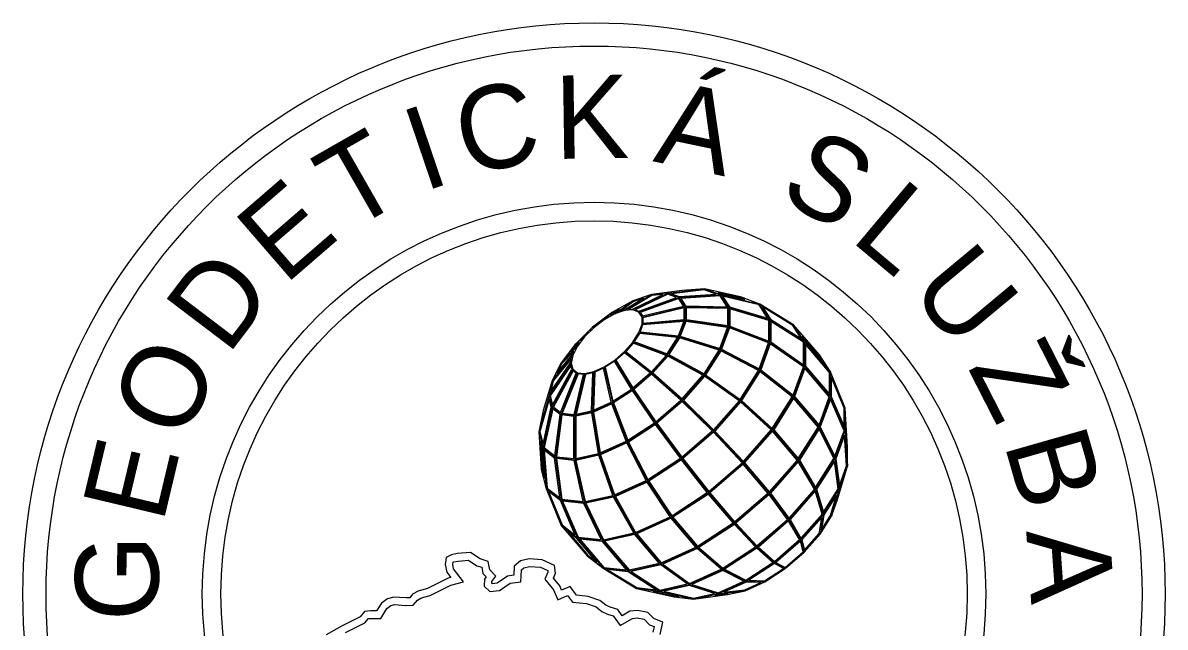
# Model space of a CAD drawing. Extents: x 70 to 280, y -123 to 174.
# Drawn here: x 204.6 to 220.99, y -1.41 to 7.26 of the extents above; entities that cross this region are included whole.
import ezdxf

# ---------------------------------------------------------------- set-up
doc = ezdxf.new("R2010")
doc.units = 0
doc.layers.add('Vrstva 63', color=7, linetype='Continuous')

msp = doc.modelspace()

# ---------------------------------------------------------------- linework, layer by layer
at = {"layer": 'Vrstva 63'}
for p, q in [((213.234, 3.131), (213.622, 3.361)), ((213.092, 3.082), (213.35, 3.268)), ((212.94, 2.998), (213.059, 3.106)), ((212.792, 2.885), (212.774, 2.891)), ((212.66, 2.755), (212.521, 2.641)), ((212.49, 2.488), (212.195, 2.128)), ((212.556, 2.619), (212.322, 2.379)), ((216.42, 1.169), (216.385, 1.729))]:
    msp.add_line(p, q, dxfattribs=at)
for points in [[(212.521, 2.641), (212.322, 2.379), (212.195, 2.128), (212.064, 1.694), (212.003, 1.389), (212.036, 0.855), (212.109, 0.577), (212.325, 0.047), (212.695, -0.388), (212.928, -0.568), (213.403, -0.858), (213.945, -0.98), (214.223, -1.011), (214.709, -0.947), (214.962, -0.891), (215.247, -0.762), (215.538, -0.571), (215.81, -0.336), (216.039, -0.077), (216.204, 0.182), (216.29, 0.42), (216.433, 0.899), (216.433, 1.17), (216.398, 1.73), (216.187, 2.249), (216.029, 2.493), (215.659, 2.928), (215.173, 3.224), (214.895, 3.326), (214.379, 3.442), (214.06, 3.418), (213.622, 3.361), (213.35, 3.268), (213.059, 3.106), (212.774, 2.891)], [(213.173, 3.124), (213.228, 3.143), (213.505, 3.307), (213.356, 3.256)], [(213.289, 3.148), (213.349, 3.153), (213.782, 3.36), (213.626, 3.348)], [(213.852, 3.364), (213.387, 3.141), (213.439, 3.122), (213.977, 3.318)], [(213.459, 3.101), (213.49, 3.053), (214.08, 3.193), (214.01, 3.302)], [(213.907, 3.372), (214.018, 3.331), (214.547, 3.367), (214.378, 3.429)], [(214.039, 3.306), (214.109, 3.198), (214.705, 3.185), (214.603, 3.344)], [(214.573, 3.385), (214.613, 3.37), (214.961, 3.288), (214.892, 3.313)], [(214.639, 3.337), (214.739, 3.183), (215.287, 3.023), (215.164, 3.212)], [(212.94, 2.322), (213.092, 2.421), (213.234, 2.544), (213.353, 2.678), (213.439, 2.814), (213.484, 2.937), (213.484, 3.038), (213.439, 3.108), (213.353, 3.139), (213.234, 3.131), (213.092, 3.082), (212.94, 2.998), (212.792, 2.885), (212.66, 2.755), (212.556, 2.619), (212.49, 2.488), (212.467, 2.374), (212.49, 2.288), (212.556, 2.237), (212.66, 2.225), (212.792, 2.254)], [(213.067, 3.095), (213.032, 3.064), (213.085, 3.093), (213.16, 3.147)], [(214.089, 3.168), (213.497, 3.028), (213.497, 2.952), (214.089, 3.003)], [(214.115, 3.171), (214.115, 3.002), (214.717, 2.916), (214.717, 3.158)], [(214.743, 3.154), (214.743, 2.909), (215.304, 2.693), (215.304, 2.99)], [(215.215, 3.182), (215.327, 3.009), (215.772, 2.727), (215.649, 2.918)], [(214.082, 2.976), (213.493, 2.925), (213.457, 2.825), (214.007, 2.768)], [(214.712, 2.89), (214.111, 2.976), (214.033, 2.762), (214.601, 2.585)], [(215.331, 2.976), (215.331, 2.681), (215.803, 2.354), (215.803, 2.676)], [(212.76, 2.859), (212.735, 2.835)], [(212.79, 2.887), (212.802, 2.896)], [(213.993, 2.742), (213.446, 2.8), (213.373, 2.685), (213.845, 2.51)], [(215.301, 2.666), (214.738, 2.883), (214.626, 2.575), (215.165, 2.293)], [(212.46, 2.54), (212.546, 2.627), (212.581, 2.674), (212.53, 2.632)], [(213.828, 2.488), (213.357, 2.663), (213.253, 2.545), (213.621, 2.253)], [(214.589, 2.561), (214.021, 2.738), (213.87, 2.499), (214.375, 2.223)], [(215.801, 2.324), (215.324, 2.653), (215.188, 2.279), (215.652, 1.916)], [(215.78, 2.765), (215.827, 2.692), (216.065, 2.412), (216.018, 2.485)], [(215.83, 2.648), (215.83, 2.334), (216.173, 1.93), (216.173, 2.244)], [(212.261, 2.23), (212.479, 2.495), (212.505, 2.548), (212.333, 2.371)], [(213.602, 2.235), (213.234, 2.526), (213.109, 2.418), (213.353, 2.02)], [(214.358, 2.202), (213.854, 2.477), (213.641, 2.236), (214.059, 1.863)], [(215.154, 2.269), (214.614, 2.551), (214.397, 2.209), (214.892, 1.856)], [(212.199, 1.78), (212.476, 2.29), (212.462, 2.343), (212.166, 1.907)], [(212.177, 1.971), (212.455, 2.379), (212.466, 2.438), (212.207, 2.122)], [(212.931, 2.303), (212.805, 2.246), (212.788, 1.701), (213.043, 1.817)], [(213.088, 2.402), (212.955, 2.316), (213.067, 1.831), (213.332, 2.004)], [(215.821, 2.303), (215.674, 1.897), (216.024, 1.485), (216.172, 1.891)], [(212.316, 1.668), (212.54, 2.232), (212.494, 2.268), (212.212, 1.748)], [(212.643, 2.214), (212.565, 2.222), (212.34, 1.658), (212.51, 1.639)], [(212.761, 1.691), (212.778, 2.238), (212.671, 2.214), (212.538, 1.642)], [(214.04, 1.844), (213.622, 2.217), (213.368, 1.997), (213.682, 1.535)], [(214.876, 1.835), (214.381, 2.188), (214.078, 1.845), (214.51, 1.421)], [(215.176, 2.255), (214.913, 1.84), (215.354, 1.439), (215.641, 1.891)], [(216.2, 2.181), (216.2, 1.897), (216.385, 1.468), (216.385, 1.728)], [(213.661, 1.519), (213.347, 1.982), (213.075, 1.804), (213.278, 1.269)], [(212.063, 1.214), (212.181, 1.744), (212.151, 1.859), (212.017, 1.389)], [(214.491, 1.403), (214.059, 1.826), (213.697, 1.513), (214.055, 1.026)], [(214.896, 1.819), (214.529, 1.402), (214.938, 0.965), (215.339, 1.418)], [(215.66, 1.872), (215.374, 1.42), (215.726, 1.006), (216.012, 1.458)], [(216.384, 1.404), (216.188, 1.858), (216.043, 1.46), (216.251, 1.039)], [(212.231, 1.046), (212.308, 1.64), (212.203, 1.721), (212.079, 1.163)], [(212.763, 1.664), (212.534, 1.614), (212.533, 1.007), (212.858, 1.079)], [(213.255, 1.256), (213.051, 1.791), (212.788, 1.672), (212.884, 1.088)], [(212.506, 1.005), (212.507, 1.612), (212.333, 1.632), (212.257, 1.033)], [(214.034, 1.01), (213.676, 1.497), (213.289, 1.244), (213.568, 0.705)], [(214.92, 0.946), (214.51, 1.384), (214.071, 1.005), (214.442, 0.534)], [(215.357, 1.399), (214.956, 0.945), (215.309, 0.53), (215.71, 0.984)], [(216.238, 1.006), (216.027, 1.432), (215.743, 0.984), (215.976, 0.593)], [(216.42, 0.901), (216.389, 1.341), (216.267, 1.003), (216.319, 0.622)], [(212.085, 0.722), (212.051, 1.156), (212.025, 1.256), (212.049, 0.857)], [(213.544, 0.692), (213.266, 1.231), (212.89, 1.061), (213.091, 0.487)], [(212.305, 0.442), (212.229, 1.014), (212.08, 1.129), (212.122, 0.583)], [(212.64, 0.39), (212.509, 0.978), (212.257, 1.006), (212.334, 0.424)], [(213.065, 0.478), (212.865, 1.053), (212.535, 0.98), (212.667, 0.39)], [(214.421, 0.518), (214.05, 0.989), (213.581, 0.682), (213.911, 0.184)], [(214.937, 0.926), (214.459, 0.513), (214.812, 0.098), (215.29, 0.512)], [(215.96, 0.569), (215.725, 0.962), (215.326, 0.509), (215.592, 0.153)], [(216.299, 0.57), (216.245, 0.967), (215.99, 0.566), (216.087, 0.236)], [(213.887, 0.171), (213.558, 0.669), (213.102, 0.463), (213.391, -0.053)], [(212.525, -0.091), (212.312, 0.403), (212.14, 0.536), (212.336, 0.055)], [(214.791, 0.082), (214.438, 0.497), (213.927, 0.163), (214.279, -0.252)], [(216.068, 0.208), (215.97, 0.541), (215.608, 0.131), (215.765, -0.135)], [(212.899, -0.157), (212.648, 0.362), (212.344, 0.396), (212.567, -0.12)], [(213.365, -0.061), (213.076, 0.454), (212.676, 0.365), (212.929, -0.158)], [(215.573, 0.134), (215.307, 0.491), (214.83, 0.079), (215.134, -0.245)], [(216.191, 0.188), (216.275, 0.483), (216.095, 0.2), (216.062, -0.016)], [(214.255, -0.264), (213.903, 0.149), (213.407, -0.075), (213.759, -0.489)], [(215.113, -0.261), (214.809, 0.062), (214.299, -0.271), (214.644, -0.567)], [(215.746, -0.155), (215.588, 0.112), (215.154, -0.263), (215.383, -0.469)], [(216.063, 0.162), (215.778, -0.161), (215.817, -0.309), (216.026, -0.071)], [(212.835, -0.479), (212.548, -0.142), (212.418, -0.042), (212.705, -0.378)], [(213.26, -0.591), (212.915, -0.186), (212.589, -0.15), (212.934, -0.555)], [(213.731, -0.497), (213.38, -0.085), (212.946, -0.181), (213.297, -0.593)], [(214.619, -0.58), (214.275, -0.285), (213.781, -0.508), (214.165, -0.786)], [(215.361, -0.485), (215.132, -0.28), (214.669, -0.582), (214.974, -0.737)], [(215.795, -0.331), (215.756, -0.181), (215.406, -0.484), (215.537, -0.555)], [(213.683, -0.876), (213.287, -0.621), (212.985, -0.587), (213.407, -0.845)], [(214.132, -0.794), (213.752, -0.52), (213.326, -0.614), (213.74, -0.881)], [(214.945, -0.752), (214.643, -0.599), (214.2, -0.799), (214.576, -0.919)], [(215.512, -0.572), (215.383, -0.502), (215.018, -0.741), (215.243, -0.748)], [(214.526, -0.931), (214.163, -0.815), (213.797, -0.896), (214.223, -0.997)], [(215.189, -0.773), (214.978, -0.766), (214.658, -0.911), (214.958, -0.878)], [(214.012, -0.974), (213.735, -0.908), (213.638, -0.897), (213.947, -0.967)], [(214.72, -0.931), (214.579, -0.946), (214.528, -0.957), (214.706, -0.934)]]:
    msp.add_lwpolyline(points, close=True, dxfattribs=at)
for points in [[(212.003, 1.389), (212.064, 1.158), (212.242, 1.021), (212.52, 0.99), (212.874, 1.068), (213.272, 1.249), (213.679, 1.515), (214.06, 1.844), (214.379, 2.206), (214.61, 2.569), (214.73, 2.9), (214.73, 3.171), (214.61, 3.358), (214.379, 3.442)], [(212.195, 2.128), (212.151, 1.91), (212.195, 1.744), (212.322, 1.646), (212.521, 1.624), (212.774, 1.68), (213.059, 1.809), (213.35, 2), (213.622, 2.235), (213.851, 2.494), (214.016, 2.753), (214.102, 2.991), (214.102, 3.185), (214.016, 3.318), (213.851, 3.379), (213.622, 3.361)], [(213.353, 3.139), (213.851, 3.379), (214.379, 3.442)], [(213.439, 3.108), (214.016, 3.318), (214.61, 3.358), (215.173, 3.224)], [(212.109, 0.577), (212.322, 0.412), (212.657, 0.375), (213.083, 0.469), (213.562, 0.686), (214.053, 1.006), (214.511, 1.402), (214.895, 1.838), (215.173, 2.274), (215.317, 2.674), (215.317, 3), (215.173, 3.224)], [(213.484, 3.038), (214.102, 3.185), (214.73, 3.171), (215.317, 3), (215.816, 2.684), (216.187, 2.249)], [(213.484, 2.937), (214.102, 2.991), (214.73, 2.9), (215.317, 2.674), (215.816, 2.329), (216.187, 1.894), (216.398, 1.404), (216.433, 0.899)], [(212.325, 0.047), (212.557, -0.133), (212.921, -0.173), (213.385, -0.071), (213.907, 0.166), (214.441, 0.514), (214.939, 0.945), (215.357, 1.419), (215.659, 1.894), (215.816, 2.329), (215.816, 2.684), (215.659, 2.928)], [(213.439, 2.814), (214.016, 2.753), (214.61, 2.569), (215.173, 2.274), (215.659, 1.894), (216.029, 1.459), (216.253, 1.005), (216.313, 0.567), (216.204, 0.182)], [(213.353, 2.678), (213.851, 2.494), (214.379, 2.206), (214.895, 1.838), (215.357, 1.419), (215.727, 0.984), (215.976, 0.568), (216.083, 0.204), (216.039, -0.077)], [(213.234, 2.544), (213.622, 2.235), (214.06, 1.844), (214.511, 1.402), (214.939, 0.945), (215.309, 0.51), (215.591, 0.132), (215.763, -0.157), (215.81, -0.336)], [(212.467, 2.374), (212.151, 1.91), (212.003, 1.389)], [(212.94, 2.322), (213.059, 1.809), (213.272, 1.249), (213.562, 0.686), (213.907, 0.166), (214.277, -0.269), (214.643, -0.584), (214.975, -0.753), (215.247, -0.762)], [(213.092, 2.421), (213.35, 2), (213.679, 1.515), (214.053, 1.006), (214.441, 0.514), (214.811, 0.08), (215.133, -0.263), (215.383, -0.486), (215.538, -0.571)], [(212.49, 2.288), (212.195, 1.744), (212.064, 1.158), (212.109, 0.577)], [(212.556, 2.237), (212.322, 1.646), (212.242, 1.021), (212.322, 0.412), (212.557, -0.133), (212.928, -0.568)], [(212.66, 2.225), (212.521, 1.624), (212.52, 0.99), (212.657, 0.375), (212.921, -0.173), (213.292, -0.608), (213.737, -0.895), (214.223, -1.011)], [(212.792, 2.254), (212.774, 1.68), (212.874, 1.068), (213.083, 0.469), (213.385, -0.071), (213.755, -0.505), (214.163, -0.801), (214.577, -0.933), (214.962, -0.891)], [(212.928, -0.568), (213.292, -0.608), (213.755, -0.505), (214.277, -0.269), (214.811, 0.08), (215.309, 0.51), (215.727, 0.984), (216.029, 1.459), (216.187, 1.894), (216.187, 2.249)], [(213.403, -0.858), (213.737, -0.895), (214.163, -0.801), (214.643, -0.584), (215.133, -0.263), (215.591, 0.132), (215.976, 0.568), (216.253, 1.005), (216.398, 1.404), (216.398, 1.73)], [(214.223, -1.011), (214.577, -0.933), (214.975, -0.753), (215.383, -0.486), (215.763, -0.157), (216.083, 0.204), (216.313, 0.567), (216.433, 0.899)], [(210.83, -0.358), (210.747, -0.373), (210.673, -0.416), (210.659, -0.513), (210.681, -0.623), (210.739, -0.7), (210.702, -0.709), (210.403, -0.859), (210.321, -0.883), (210.27, -0.899), (210.189, -0.942), (210.149, -0.993), (210.093, -0.994), (209.922, -0.982), (209.833, -1.007), (209.745, -1.07), (209.675, -1.181), (209.585, -1.18), (209.502, -1.187), (209.438, -1.267), (209.178, -1.396), (208.951, -1.522)], [(209.227, -1.49), (209.507, -1.352), (209.556, -1.289), (209.589, -1.287), (209.734, -1.288), (209.823, -1.145), (209.88, -1.105), (209.933, -1.09), (210.091, -1.101), (210.201, -1.097), (210.259, -1.026), (210.311, -0.998), (210.352, -0.985), (210.442, -0.958), (210.738, -0.809), (210.922, -0.765), (210.78, -0.578), (210.767, -0.51), (210.771, -0.482), (210.785, -0.474), (210.844, -0.464), (210.995, -0.45), (211.112, -0.531), (211.184, -0.554), (211.2, -0.645), (211.246, -0.69), (211.221, -0.723), (211.218, -0.823), (211.299, -0.901), (211.44, -0.885), (211.592, -0.784), (211.743, -0.762), (211.754, -0.589), (211.787, -0.56), (211.871, -0.543), (212.025, -0.553), (212.131, -0.601), (212.134, -0.623), (212.088, -0.725), (212.211, -0.876), (212.277, -1.019), (212.416, -0.96), (212.486, -1.053), (212.687, -1.076), (212.826, -1.124), (212.907, -1.191), (212.988, -1.227), (213.07, -1.252), (213.169, -1.392), (213.346, -1.289), (213.415, -1.28), (213.514, -1.3), (213.591, -1.378), (213.659, -1.406), (213.641, -1.486)], [(213.743, -1.519), (213.782, -1.342), (213.652, -1.288), (213.567, -1.202), (213.419, -1.173), (213.311, -1.186), (213.2, -1.251), (213.136, -1.161), (213.025, -1.127), (212.963, -1.1), (212.88, -1.03), (212.71, -0.972), (212.544, -0.953), (212.451, -0.83), (212.33, -0.881), (212.302, -0.819), (212.212, -0.709), (212.243, -0.639), (212.229, -0.529), (212.051, -0.448), (211.864, -0.435), (211.738, -0.462), (211.651, -0.538), (211.642, -0.669), (211.553, -0.682), (211.403, -0.782), (211.337, -0.79), (211.326, -0.779), (211.326, -0.76), (211.387, -0.681), (211.299, -0.593), (211.277, -0.471), (211.159, -0.434), (211.023, -0.341), (210.83, -0.358)]]:
    msp.add_lwpolyline(points, dxfattribs=at)
for radius in [8.197, 7.865, 7.865, 5.622, 5.622, 5.356]:
    msp.add_circle((212.795, -0.937), radius, dxfattribs=at)

# ---------------------------------------------------------------- texts
for s, rotation, p in [('Á', 348.0844, (213.63, 5.275)), ('C', 12.7701, (210.96, 5.056)), ('K', 0.8492, (212.237, 5.306)), ('I', 18.7306, (210.347, 4.833)), ('T', 29.797, (209.285, 4.256)), ('S', 331.0575, (215.412, 4.758)), ('E', 40.8634, (208.354, 3.486)), ('L', 319.9911, (216.457, 4.149)), ('U', 309.7687, (217.301, 3.419)), ('D', 52.7843, (207.536, 2.473)), ('Ž', 297.0038, (218.152, 2.315)), ('O', 65.5492, (206.912, 1.227)), ('B', 285.9374, (218.677, 1.226)), ('E', 76.6156, (206.606, 0.058)), ('A', 274.0165, (218.997, -0.035)), ('G', 89.3804, (206.539, -1.334))]:
    msp.add_text(s, height=1.196, rotation=rotation, dxfattribs=at).set_placement(p)

doc.saveas('drawing.dxf')
